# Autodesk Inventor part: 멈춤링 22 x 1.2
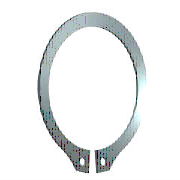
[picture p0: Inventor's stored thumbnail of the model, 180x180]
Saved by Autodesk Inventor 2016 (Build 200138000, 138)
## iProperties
IsCustomPart: 0
Created: 2015-11
Part Number: 멈춤링 22 x 1.2
Material: 스테인리스강
Description: 리테이닝 링(C형)
Document SubType Name: Modeling
Standard: KS B 1336
Designer: mdu
Standards Organization: KS
Language: ko-KR
Size Designation: 22 x 1.2
Categories: <MemberInstance><Categories><Category DisplayName="샤프트 부품" InternalName="7f7aeb1f-a693-4053-b835-cee3144e0d98" Mnemonic="SHFT"><Category DisplayName="써클립" Inter
Density: 8.08 g/cm^3
Mass: 1.87978 g
Surface Area: 5.91219 cm^2
Volume: 0.232646 cm^3
Appearance: 반광택
Author: mdu
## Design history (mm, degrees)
sketch "스케치1"
  geometry: L1 (-6, 0)-(6, 0) reference; L2 (0, 20.189)-(0, -80.536) reference; L3 (-48.09, 0)-(48.09, 0) reference; L4 (-0.5, -21.488)-(-0.5, -25.588); L5 (-0.5, -6.54)-(-0.5, -13.29); L6 (-2.795, 2.7)-(3.672, 2.7); L7 (0.5, -6.54)-(0.5, -13.29); L8 (0.5, -21.488)-(0.5, -25.588); C1 r 1 at (-2, -23.437); C2 r 1 at (2, -23.437); A1 r 10.5 centre (0, -11) between (0.5, -21.488) and (-0.5, -21.488); A2 r 13.025 centre (0, -10.325) between (5.149, -22.289) and (-5.149, -22.289); A3 r 14.597 centre (0, -11) between (-2.318, -25.411) and (-0.5, -25.588); A4 r 2 centre (-2, -23.437) between (-3.97, -23.781) and (-2.318, -25.411); A5 r 2 centre (-5.94, -24.126) between (-3.97, -23.781) and (-5.149, -22.289); A6 r 2 centre (5.94, -24.126) between (5.149, -22.289) and (3.97, -23.781); A7 r 2 centre (2, -23.437) between (2.318, -25.411) and (3.97, -23.781); A8 r 14.597 centre (0, -11) between (0.5, -25.588) and (2.318, -25.411)
  constraints: 16 point on circle, 12 end point, 10 centre point, 9 symmetric about line, 5 point on line, 4 tangent, 3 coincident, 2 horizontal, 1 perpendicular, 1 vertical, 5 other
  dimensions: "d0" = 21 diameter of A1 (= ND); "d1" = 4.1 distance of L4.end L4.start (= SRB2); "d6" = 0.5 distance between parallel lines of L2 L5 (= 0.25 x SD5); "d7" = 2.7 distance between parallel lines of L6 L3 (= SRB1); "d8" = 0.675 distance of A1.centre A2.centre (= 0.25 x SRB1); "d9" = 2 radius of A4 (= SD5); "d10" = 2 radius of A5 (= SD5); "d11" = 1.5 distance from line of L4 A4.centre (= 0.75 x SD5); "d12" = 2 diameter of C1 (= SD5); "d13" = 2 diameter of C2 (= SD5); "d14" = 11 distance from line of A1.centre L1 (= 0.5 x WD)
extrude "본체" new body sketch "스케치1" distance "d2" = 1.2 (= SD); taper "d3" = 0 deg
workaxis "Work Axis1"
workplane "Work Plane1"
body "Solid1"
other parameters: "WD" = 22 (= WDMIN) [user parameter; used in 1 equation term], "SD" = 1.2 [user parameter; used in 1 equation term], "SRB1" = 2.7 [user parameter; used in 2 equation terms], "ND" = 21 [user parameter; used in 1 equation term], "SRB2" = 4.1 [user parameter; used in 1 equation term], "SD5" = 2 [user parameter; used in 6 equation terms], "d15" = 0, "d16" = 0, "d17" = 0, "d41" = 0, "d42" = 0, "WDMIN" = 22 [user parameter; used in 1 equation term], "SD3" = 20.5 [user parameter], "WDMAX" = 24 [user parameter]
